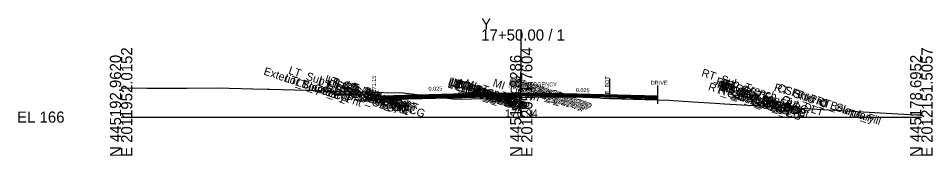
# Model space of a CAD drawing. Extents: x -26 to 3203, y -10 to 9532.
# Drawn here: x 974.3 to 1202.8, y 1490.3 to 1524.8 of the extents above; entities that cross this region are included whole.
import ezdxf

# ---------------------------------------------------------------- set-up
doc = ezdxf.new("R2010")
doc.units = 0
for name, color, linetype in [('Default', 7, 'Continuous'), ('Exist Cross Section Cell', 7, 'Continuous'), ('Exist XS Center Line Elevation Label', 7, 'Continuous'), ('Exist XS Ground Line', 7, 'Continuous'), ('Prop CMT Conc Surface', 7, 'Continuous'), ('Prop CMT Concrete Structures', 7, 'Continuous'), ('Prop CMT Pvmt Course 1', 7, 'Continuous'), ('Prop CMT Pvmt Course 1 CG', 7, 'Continuous'), ('Prop CMT Pvmt Course 2', 7, 'Continuous'), ('Prop CMT Pvmt Course 3', 7, 'Continuous'), ('Prop CMT Pvmt Surface', 7, 'Continuous'), ('Prop CMT Pvmt Wedge Surface 3', 7, 'Continuous'), ('Prop CMT Shear Line', 7, 'Continuous'), ('Prop CMT Shear Line Text', 7, 'Continuous'), ('Prop CMT Slope Grass', 7, 'Continuous'), ('Prop CMT Subgrade Earthwork', 7, 'Continuous'), ('Prop XS Hydro Elevations', 7, 'Continuous'), ('Prop XS Label Text', 7, 'Continuous'), ('Prop XS SE Text', 7, 'Continuous'), ('Prop XS Side Slope Text', 7, 'Continuous'), ('Scratch_Level_0', 7, 'Continuous')]:
    doc.layers.add(name, color=color, linetype=linetype)

msp = doc.modelspace()

# ---------------------------------------------------------------- linework, layer by layer
at = {"layer": 'Exist Cross Section Cell'}
for p, q in [((1100, 1500), (1100, 1521.98)), ((1000, 1500), (1100, 1500)), ((1100, 1500), (1200, 1500))]:
    msp.add_line(p, q, dxfattribs=at)
at = {"layer": 'Exist XS Ground Line'}
msp.add_lwpolyline([(1000, 1507.32), (1000.63, 1507.33), (1006.51, 1507.26), (1009.99, 1507.29), (1016.53, 1507.26), (1024.08, 1507.3), (1032.89, 1507.09), (1036.59, 1507.02), (1037.1, 1507.02), (1046.61, 1506.78), (1047.42, 1506.76), (1056.64, 1506.4), (1057.01, 1506.39), (1065.67, 1506.17), (1070.46, 1506.04), (1083.66, 1504.48), (1091.29, 1504.7), (1098.66, 1504.9), (1099.83, 1504.94), (1100.26, 1504.94), (1102.16, 1504.97), (1102.78, 1504.98), (1104.86, 1505.04), (1105.28, 1505.05), (1105.65, 1505.05), (1107.79, 1505.08), (1110.29, 1505.1), (1110.82, 1505.1), (1112.93, 1505.08), (1115.28, 1504.98), (1115.62, 1504.97), (1117.78, 1504.89), (1119.65, 1504.79), (1120.29, 1504.75), (1122.06, 1504.68), (1136.85, 1504.21), (1142.87, 1503.85), (1148.5, 1503.47), (1150.79, 1503.33), (1197.01, 1500.64), (1198.91, 1500.59), (1200, 1500.57)], dxfattribs=at)
at = {"layer": 'Prop CMT Conc Surface'}
for points in [[(1058.68, 1505.74), (1053.68, 1505.84)], [(1063.18, 1505.15), (1063.18, 1505.65), (1062.68, 1505.65)], [(1065.18, 1505.28), (1063.18, 1505.15)]]:
    msp.add_lwpolyline(points, dxfattribs=at)
at = {"layer": 'Prop CMT Concrete Structures'}
for p, q in [((1092.02, 1505.96), (1092.02, 1506.33)), ((1107.2, 1505.97), (1107.2, 1506.34))]:
    msp.add_line(p, q, dxfattribs=at)
for points in [[(1053.68, 1505.51), (1053.68, 1505.84)], [(1053.68, 1505.84), (1058.68, 1505.74)], [(1058.68, 1505.41), (1053.68, 1505.51)], [(1058.68, 1505.74), (1058.68, 1505.41)], [(1065.18, 1505.28), (1063.18, 1505.15), (1063.18, 1505.65), (1062.68, 1505.65)], [(1062.68, 1505.65), (1062.68, 1504.64), (1065.18, 1504.7)], [(1065.18, 1504.7), (1065.18, 1505.28)], [(1092.02, 1505.96), (1107.2, 1505.97)]]:
    msp.add_lwpolyline(points, dxfattribs=at)
at = {"layer": 'Prop CMT Pvmt Course 1'}
for points in [[(1092.02, 1505.96), (1065.18, 1505.28)], [(1065.18, 1505.03), (1092.02, 1505.71)], [(1065.18, 1505.28), (1065.18, 1505.03)], [(1092.02, 1505.96), (1107.2, 1505.97)], [(1092.02, 1505.71), (1092.02, 1505.96)], [(1092.02, 1505.71), (1092.02, 1505.96)], [(1107.2, 1505.72), (1092.02, 1505.71)], [(1107.2, 1505.97), (1107.2, 1505.72)], [(1107.2, 1505.97), (1134.13, 1505.3)], [(1107.2, 1505.72), (1107.2, 1505.97)], [(1134.13, 1505.05), (1107.2, 1505.72)]]:
    msp.add_lwpolyline(points, dxfattribs=at)
for points in [[(1092.02, 1505.71), (1092.02, 1505.83), (1092.02, 1505.83), (1092.02, 1505.71)], [(1107.2, 1505.72), (1107.2, 1505.85), (1107.2, 1505.85), (1107.2, 1505.72)]]:
    msp.add_lwpolyline(points, close=True, dxfattribs=at)
at = {"layer": 'Prop CMT Pvmt Course 1 CG'}
for points in [[(1065.18, 1504.7), (1062.18, 1504.63), (1061.84, 1504.28)], [(1061.84, 1504.28), (1065.18, 1504.37)], [(1065.18, 1504.37), (1065.18, 1504.7)]]:
    msp.add_lwpolyline(points, dxfattribs=at)
at = {"layer": 'Prop CMT Pvmt Course 2'}
for points in [[(1092.02, 1505.71), (1065.18, 1505.03)], [(1065.18, 1504.7), (1092.02, 1505.37)], [(1065.18, 1505.03), (1065.18, 1504.7)], [(1092.02, 1505.71), (1107.2, 1505.72)], [(1092.02, 1505.37), (1092.02, 1505.71)], [(1092.02, 1505.37), (1092.02, 1505.71)], [(1107.2, 1505.39), (1092.02, 1505.37)], [(1107.2, 1505.72), (1107.2, 1505.39)], [(1107.2, 1505.39), (1107.2, 1505.72)], [(1107.2, 1505.72), (1134.13, 1505.05)], [(1133.99, 1504.72), (1107.2, 1505.39)]]:
    msp.add_lwpolyline(points, dxfattribs=at)
at = {"layer": 'Prop CMT Pvmt Course 3'}
for points in [[(1092.02, 1505.37), (1065.18, 1504.7)], [(1065.18, 1504.37), (1092.02, 1505.04)], [(1065.18, 1504.7), (1065.18, 1504.37)], [(1092.02, 1505.37), (1107.2, 1505.39)], [(1092.02, 1505.04), (1092.02, 1505.37)], [(1092.02, 1505.04), (1092.02, 1505.37)], [(1099.83, 1505.05), (1092.02, 1505.04)], [(1107.2, 1505.39), (1134.13, 1504.72)], [(1107.2, 1505.39), (1134.13, 1504.72)], [(1134.13, 1504.39), (1122.06, 1504.69)]]:
    msp.add_lwpolyline(points, dxfattribs=at)
at = {"layer": 'Prop CMT Pvmt Surface'}
for points in [[(1092.02, 1505.96), (1065.18, 1505.28)], [(1092.02, 1505.96), (1107.2, 1505.97)], [(1107.2, 1505.97), (1134.13, 1505.3)]]:
    msp.add_lwpolyline(points, dxfattribs=at)
at = {"layer": 'Prop CMT Pvmt Wedge Surface 3'}
msp.add_lwpolyline([(1107.2, 1505.39), (1134.13, 1504.72)], dxfattribs=at)
at = {"layer": 'Prop CMT Shear Line'}
msp.add_line((1134.13, 1503.3), (1134.13, 1507.88), dxfattribs=at)
at = {"layer": 'Prop CMT Slope Grass'}
msp.add_lwpolyline([(1062.68, 1505.65), (1053.18, 1505.84), (1050.83, 1506.63)], dxfattribs=at)
at = {"layer": 'Prop CMT Subgrade Earthwork'}
for p, q in [((1099.83, 1505.05), (1099.83, 1504.94)), ((1122.06, 1504.69), (1122.06, 1504.68))]:
    msp.add_line(p, q, dxfattribs=at)
for points in [[(1065.18, 1504.37), (1061.84, 1504.28), (1060.42, 1505.7)], [(1092.02, 1505.04), (1065.18, 1504.37)], [(1092.02, 1505.04), (1099.83, 1505.05)], [(1122.06, 1504.69), (1134.13, 1504.39)]]:
    msp.add_lwpolyline(points, dxfattribs=at)
at = {"layer": 'Prop XS Label Text'}
for p, q in [((1099.83, 1509.94), (1099.83, 1504.94)), ((1122.06, 1509.68), (1122.06, 1504.68))]:
    msp.add_line(p, q, dxfattribs=at)

# ---------------------------------------------------------------- texts
at = {"layer": 'Default'}
msp.add_text('-', height=0.0001, dxfattribs=at).set_placement((1000, 1500))
at = {"layer": 'Exist Cross Section Cell'}
for s, p in [('Y', (1090, 1521.98)), ('17+50.00 / 1', (1090, 1519.18)), ('EL 166', (974, 1498.6))]:
    msp.add_text(s, height=2.8, dxfattribs=at).set_placement(p)
for s, p in [('N 445192.9620', (1000, 1490)), ('E 2011952.0152', (1002.8, 1490)), ('N 445185.8286', (1100, 1490)), ('E 2012051.7604', (1102.8, 1490)), ('N 445178.6952', (1200, 1490)), ('E 2012151.5057', (1202.8, 1490))]:
    msp.add_text(s, height=2.8, rotation=90, dxfattribs=at).set_placement(p)
at = {"layer": 'Exist XS Center Line Elevation Label'}
msp.add_text('170.94', height=2, dxfattribs=at).set_placement((1095.96, 1499.94))
at = {"layer": 'Prop CMT Shear Line Text'}
for s, p in [('EMERGENCY', (1100.01, 1507.69)), ('DRIVE', (1132.36, 1508.1)), ('ACCESS', (1101.46, 1506.38))]:
    msp.add_text(s, height=1, rotation=360, dxfattribs=at).set_placement(p)
at = {"layer": 'Prop XS Hydro Elevations'}
msp.add_text('171.15', height=1, rotation=90, dxfattribs=at).set_placement((1063.68, 1506.15))
at = {"layer": 'Prop XS Label Text'}
for p in [(1099.73, 1505.96), (1121.96, 1505.71)]:
    msp.add_text('E. EOT', height=1, rotation=90, dxfattribs=at).set_placement(p)
at = {"layer": 'Prop XS SE Text'}
for rotation, p in [(1.4321, (1076.84, 1506.58)), (358.5679, (1113.63, 1506.32))]:
    msp.add_text('0.025', height=1, rotation=rotation, dxfattribs=at).set_placement(p)
at = {"layer": 'Prop XS Side Slope Text'}
msp.add_text('3:1', height=1, rotation=341.5651, dxfattribs=at).set_placement((1051.49, 1507.2))
at = {"layer": 'Scratch_Level_0'}
for s, p in [('Exterior Boundary', (1035.47, 1510.69)), ('LT_Slope_Cut', (1040.68, 1508.96)), ('LT_Sub_Trench_Out_DLT', (1041.67, 1510.9)), ('RT_Sub_Trench_Out_DLT', (1144.88, 1510.31)), ('LT_CSLP_Pnt', (1043.54, 1508)), ('LT_CG1_Shelf_Out', (1049.1, 1507.93)), ('LT_CG_Top_Face', (1050.77, 1508.73)), ('LT_CG_Top_BOC', (1051.24, 1508.41)), ('LT_CG_Bot_BOC', (1051.28, 1507.38)), ('LT_CG_Top_Gut', (1051.7, 1507.93)), ('LT_Sub_OEOT_CG', (1052.88, 1507.41)), ('LT_CG_Bot_IE', (1055.29, 1506.94)), ('LT_Sub_OEOT', (1055.45, 1506.56)), ('LT_PV2_OEOT', (1055.54, 1507.19)), ('LT_PV3_OEOT', (1055.54, 1506.86)), ('LT_PV1_OEOT', (1056.08, 1507.26)), ('LT_Sub_OEEOP', (1081.47, 1507.5)), ('LT_PV2_OEEOP', (1081.56, 1508.14)), ('LT_PV3_OEEOP', (1081.56, 1507.8)), ('LT_PV1_OEEOP', (1082.09, 1508.08)), ('LT_PV2_IEEOP', (1082.17, 1507.93)), ('LT_PV1_IEEOP', (1082.71, 1507.88)), ('LT_PV2_PGL1', (1083.05, 1507.64)), ('LT_PV3_PGL1', (1083.05, 1507.31)), ('LT_PV2_PGL', (1083.36, 1507.54)), ('LT_PV4_PGL', (1083.36, 1506.87)), ('LT_PV1_PGL', (1083.9, 1507.61)), ('MI_Face In', (1084.02, 1507.74)), ('MI_Top In', (1085.68, 1507.68)), ('MI_Crown', (1092.72, 1507.77)), ('RT_Sub_OEEOP', (1096.61, 1507.54)), ('RT_PV2_OEEOP', (1096.7, 1508.17)), ('RT_PV3_OEEOP', (1096.7, 1507.84)), ('RT_PV1_OEEOP', (1097.23, 1508.12)), ('RT_PV2_IEEOP', (1097.31, 1507.97)), ('MI_Face Out', (1097.64, 1508.27)), ('MI_Top Out', (1097.8, 1508.22)), ('RT_PV1_IEEOP', (1097.85, 1507.91)), ('RT_PV2_PGL1', (1098.19, 1507.67)), ('RT_PV3_PGL1', (1098.19, 1507.34)), ('RT_PV2_PGL', (1098.5, 1507.57)), ('RT_PV4_PGL', (1098.5, 1506.9)), ('MI_Bot Out', (1098.59, 1507.79)), ('RT_PV1_PGL', (1099.04, 1507.64)), ('RT_Sub_OEOT_CG', (1146.58, 1506.83)), ('RT_CG_Top_Face', (1148.47, 1508.15)), ('RT_CG1_Shelf_Out', (1148.8, 1507.34)), ('RT_PV2_OEOT', (1149.24, 1506.61)), ('RT_CG_Top_Gut', (1149.4, 1507.34)), ('RT_PV1_OEOT', (1149.77, 1506.68)), ('RT_CG_Top_BOC', (1149.94, 1507.82)), ('RT_CG_Bot_BOC', (1149.97, 1506.8)), ('RT_Shld_O', (1163.02, 1506.64)), ('LT_Sub_OEOP', (1052.14, 1506.46)), ('RT_CG_Bot_IE', (1148.99, 1506.35)), ('RT_Sub_OEOT', (1149.15, 1505.97)), ('RT_PV3_OEOT', (1149.24, 1506.27)), ('RT_Sub_OEOP', (1152.52, 1505.88)), ('CSLP_Pnt', (1163.84, 1506.55)), ('Exterior Boundary', (1167.58, 1505.3)), ('RT_Slope_Fill', (1173.58, 1503.3))]:
    msp.add_text(s, height=2, rotation=341.5651, dxfattribs=at).set_placement(p)

doc.saveas('drawing.dxf')
